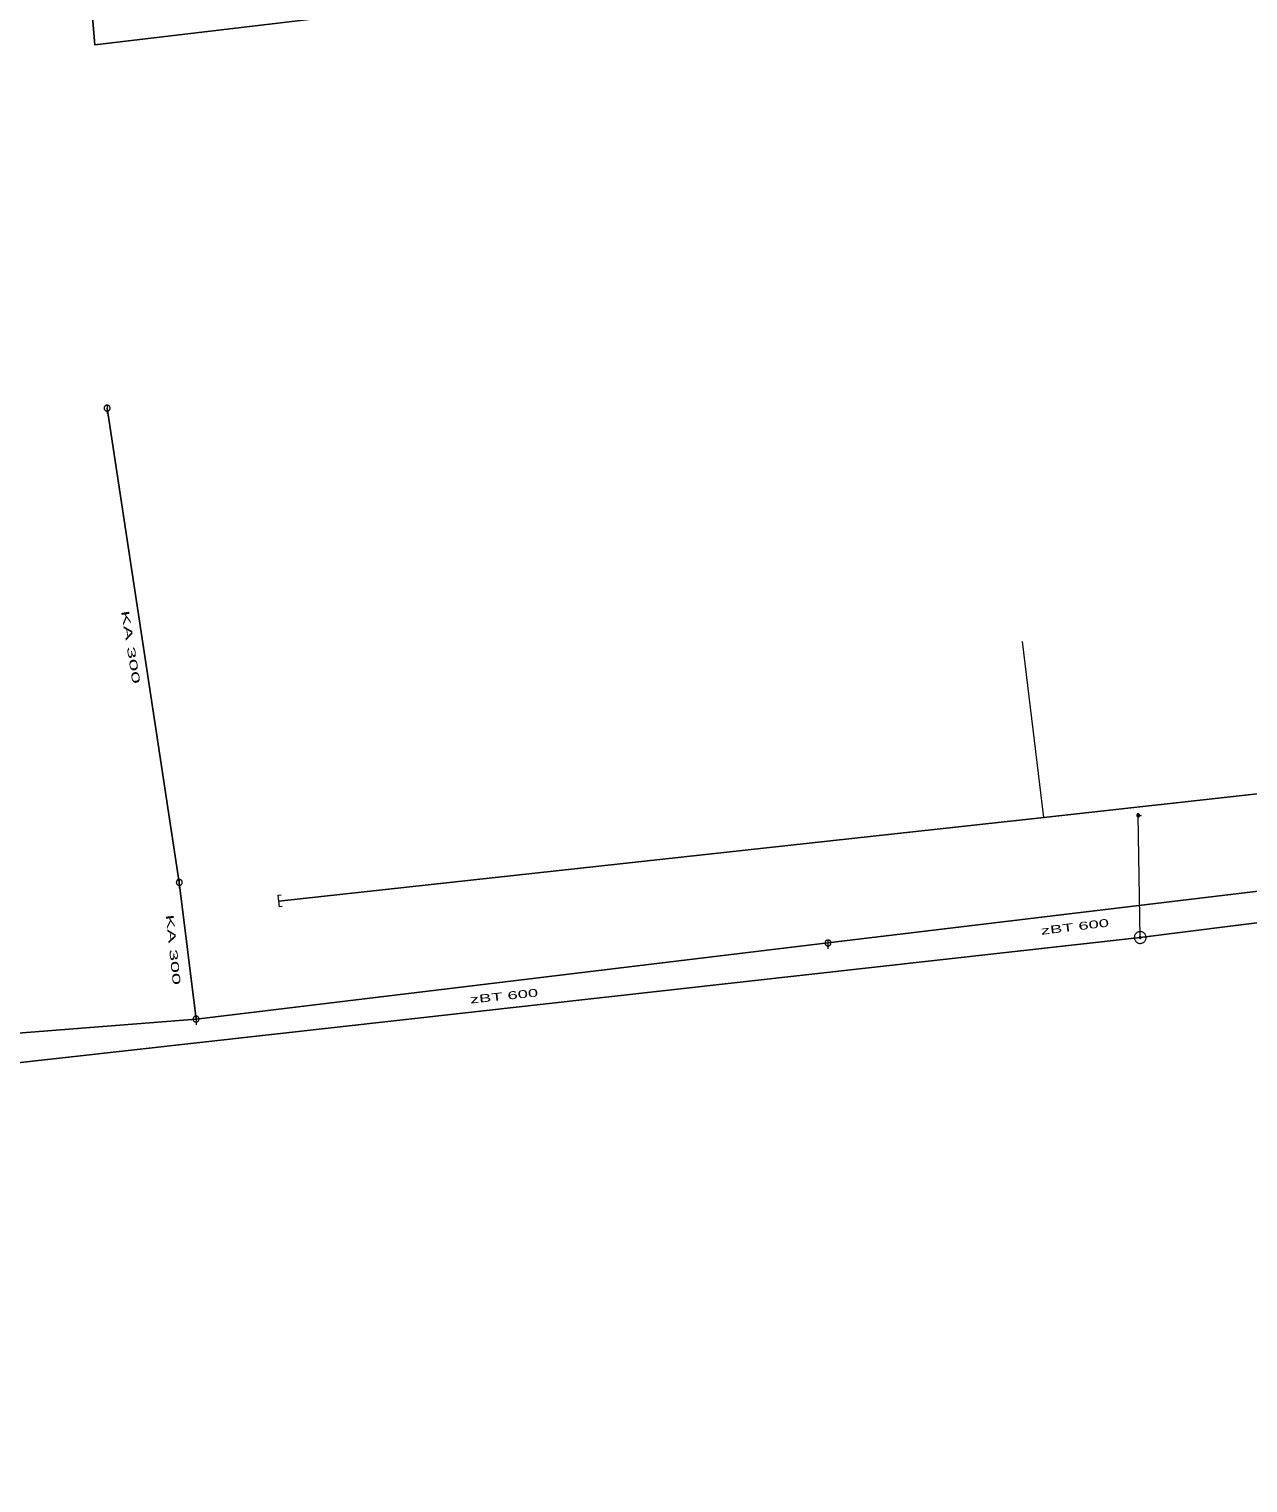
# Model space of a CAD drawing. Extents: x -687515 to -686506, y -974029 to -973461.
# Drawn here: x -686958.8 to -686855.3, y -973700.3 to -973577 of the extents above; entities that cross this region are included whole.
import ezdxf
from ezdxf.enums import TextEntityAlignment as Align

# ---------------------------------------------------------------- set-up
doc = ezdxf.new("R2010")
doc.units = 0
doc.header["$LTSCALE"] = 0.27
for name, color, linetype, lineweight in [('1', 7, 'Continuous', 13), ('13', 7, 'Continuous', 13), ('14', 7, 'Continuous', 25), ('17', 7, 'Continuous', 25), ('22', 7, 'Continuous', 13), ('47', 7, 'Continuous', 13), ('9', 7, 'Continuous', 13)]:
    doc.layers.add(name, color=color, linetype=linetype, lineweight=lineweight)

msp = doc.modelspace()

# ---------------------------------------------------------------- linework, layer by layer
at = {"layer": '13'}
msp.add_line((-686872.671, -973643.865), (-686874.464, -973628.946), dxfattribs=at)
at = {"layer": '14'}
for p, q in [((-686952.143, -973609.144), (-686946.019, -973649.374)), ((-686946.019, -973649.374), (-686944.599, -973660.967)), ((-686848.883, -973649.437), (-686890.976, -973654.512)), ((-686890.976, -973654.512), (-686944.599, -973660.967)), ((-686944.599, -973660.967), (-686987.741, -973664.387))]:
    msp.add_line(p, q, dxfattribs=at)
at = {"layer": '14', "lineweight": 13}
msp.add_line((-686864.483, -973654.051), (-686864.649, -973643.689), dxfattribs=at)
at = {"layer": '17'}
for p, q in [((-686760.428, -973640.909), (-686864.483, -973654.051)), ((-686864.483, -973654.051), (-687064.409, -973676.368))]:
    msp.add_line(p, q, dxfattribs=at)
for points in [[(-686645.309, -973464.46), (-686646.34, -973464.75), (-686680.188, -973471.317), (-686771.188, -973470.317), (-686761.188, -973557.317), (-686894.188, -973571.317), (-686953.188, -973578.317), (-686955.188, -973554.317), (-687116.188, -973577.317), (-687229.188, -973601.317), (-687468.188, -973649.317), (-687458.188, -973700.317)], [(-686937.575, -973650.962), (-686872.671, -973643.864), (-686761.239, -973631.509)]]:
    msp.add_lwpolyline(points, dxfattribs=at)
at = {"layer": '22'}
for p, q in [((-686952.142, -973608.892), (-686952.143, -973609.636)), ((-686946.018, -973649.122), (-686946.019, -973649.865)), ((-686890.975, -973654.26), (-686890.976, -973655.004)), ((-686944.598, -973660.715), (-686944.599, -973661.458))]:
    msp.add_line(p, q, dxfattribs=at)
for points in [[(-686951.891, -973609.144), (-686951.892, -973609.118), (-686951.896, -973609.092), (-686951.902, -973609.066), (-686951.912, -973609.042), (-686951.924, -973609.018), (-686951.938, -973608.996), (-686951.955, -973608.975), (-686951.973, -973608.957), (-686951.994, -973608.94), (-686952.016, -973608.926), (-686952.04, -973608.914), (-686952.064, -973608.904), (-686952.09, -973608.898), (-686952.116, -973608.894), (-686952.142, -973608.892), (-686952.168, -973608.893), (-686952.194, -973608.897), (-686952.22, -973608.903), (-686952.245, -973608.913), (-686952.268, -973608.925), (-686952.29, -973608.939), (-686952.311, -973608.956), (-686952.329, -973608.974), (-686952.346, -973608.995), (-686952.36, -973609.017), (-686952.372, -973609.041), (-686952.382, -973609.065), (-686952.389, -973609.091), (-686952.393, -973609.117), (-686952.395, -973609.143), (-686952.394, -973609.169), (-686952.39, -973609.195), (-686952.383, -973609.221), (-686952.373, -973609.246), (-686952.361, -973609.269), (-686952.347, -973609.291), (-686952.33, -973609.312), (-686952.312, -973609.33), (-686952.291, -973609.347), (-686952.269, -973609.361), (-686952.246, -973609.373), (-686952.221, -973609.383), (-686952.195, -973609.39), (-686952.169, -973609.394), (-686952.143, -973609.396), (-686952.117, -973609.395), (-686952.091, -973609.391), (-686952.065, -973609.384), (-686952.041, -973609.374), (-686952.017, -973609.362), (-686951.995, -973609.348), (-686951.974, -973609.331), (-686951.956, -973609.313), (-686951.939, -973609.292), (-686951.925, -973609.27), (-686951.913, -973609.247), (-686951.903, -973609.222), (-686951.897, -973609.196), (-686951.893, -973609.17)], [(-686945.767, -973649.374), (-686945.768, -973649.348), (-686945.772, -973649.322), (-686945.778, -973649.296), (-686945.788, -973649.272), (-686945.8, -973649.248), (-686945.814, -973649.226), (-686945.831, -973649.205), (-686945.849, -973649.187), (-686945.87, -973649.17), (-686945.892, -973649.156), (-686945.916, -973649.144), (-686945.94, -973649.134), (-686945.966, -973649.128), (-686945.992, -973649.124), (-686946.018, -973649.122), (-686946.044, -973649.123), (-686946.07, -973649.127), (-686946.096, -973649.133), (-686946.121, -973649.143), (-686946.144, -973649.155), (-686946.166, -973649.169), (-686946.187, -973649.186), (-686946.205, -973649.204), (-686946.222, -973649.225), (-686946.236, -973649.247), (-686946.248, -973649.271), (-686946.258, -973649.295), (-686946.265, -973649.321), (-686946.269, -973649.347), (-686946.271, -973649.373), (-686946.27, -973649.399), (-686946.266, -973649.425), (-686946.259, -973649.451), (-686946.249, -973649.476), (-686946.237, -973649.499), (-686946.223, -973649.521), (-686946.206, -973649.542), (-686946.188, -973649.56), (-686946.167, -973649.577), (-686946.145, -973649.591), (-686946.122, -973649.603), (-686946.097, -973649.613), (-686946.071, -973649.62), (-686946.045, -973649.624), (-686946.019, -973649.625), (-686945.993, -973649.625), (-686945.967, -973649.621), (-686945.941, -973649.614), (-686945.917, -973649.604), (-686945.893, -973649.592), (-686945.871, -973649.578), (-686945.85, -973649.561), (-686945.832, -973649.543), (-686945.815, -973649.522), (-686945.801, -973649.5), (-686945.789, -973649.477), (-686945.779, -973649.452), (-686945.773, -973649.426), (-686945.769, -973649.4)], [(-686890.724, -973654.512), (-686890.725, -973654.486), (-686890.729, -973654.46), (-686890.735, -973654.434), (-686890.745, -973654.41), (-686890.757, -973654.386), (-686890.771, -973654.364), (-686890.788, -973654.343), (-686890.806, -973654.325), (-686890.827, -973654.308), (-686890.849, -973654.294), (-686890.873, -973654.282), (-686890.897, -973654.272), (-686890.923, -973654.266), (-686890.949, -973654.262), (-686890.975, -973654.26), (-686891.001, -973654.261), (-686891.027, -973654.265), (-686891.053, -973654.271), (-686891.078, -973654.281), (-686891.101, -973654.293), (-686891.123, -973654.307), (-686891.144, -973654.324), (-686891.162, -973654.342), (-686891.179, -973654.363), (-686891.193, -973654.385), (-686891.205, -973654.409), (-686891.215, -973654.433), (-686891.222, -973654.459), (-686891.226, -973654.485), (-686891.228, -973654.511), (-686891.227, -973654.537), (-686891.223, -973654.563), (-686891.216, -973654.589), (-686891.206, -973654.614), (-686891.194, -973654.637), (-686891.18, -973654.659), (-686891.163, -973654.68), (-686891.145, -973654.698), (-686891.124, -973654.715), (-686891.102, -973654.729), (-686891.079, -973654.741), (-686891.054, -973654.751), (-686891.028, -973654.758), (-686891.002, -973654.762), (-686890.976, -973654.764), (-686890.95, -973654.763), (-686890.924, -973654.759), (-686890.898, -973654.752), (-686890.874, -973654.742), (-686890.85, -973654.73), (-686890.828, -973654.716), (-686890.807, -973654.699), (-686890.789, -973654.681), (-686890.772, -973654.66), (-686890.758, -973654.638), (-686890.746, -973654.615), (-686890.736, -973654.59), (-686890.73, -973654.564), (-686890.726, -973654.538)], [(-686944.347, -973660.967), (-686944.348, -973660.941), (-686944.352, -973660.915), (-686944.358, -973660.889), (-686944.368, -973660.865), (-686944.38, -973660.841), (-686944.394, -973660.819), (-686944.411, -973660.798), (-686944.429, -973660.78), (-686944.45, -973660.763), (-686944.472, -973660.749), (-686944.496, -973660.737), (-686944.52, -973660.727), (-686944.546, -973660.721), (-686944.572, -973660.717), (-686944.598, -973660.715), (-686944.624, -973660.716), (-686944.65, -973660.72), (-686944.676, -973660.726), (-686944.701, -973660.736), (-686944.724, -973660.748), (-686944.746, -973660.762), (-686944.767, -973660.779), (-686944.785, -973660.797), (-686944.802, -973660.818), (-686944.816, -973660.84), (-686944.828, -973660.864), (-686944.838, -973660.888), (-686944.845, -973660.914), (-686944.849, -973660.94), (-686944.851, -973660.966), (-686944.85, -973660.992), (-686944.846, -973661.018), (-686944.839, -973661.044), (-686944.829, -973661.069), (-686944.817, -973661.092), (-686944.803, -973661.114), (-686944.786, -973661.135), (-686944.768, -973661.153), (-686944.747, -973661.17), (-686944.725, -973661.184), (-686944.702, -973661.196), (-686944.677, -973661.206), (-686944.651, -973661.213), (-686944.625, -973661.217), (-686944.599, -973661.218), (-686944.573, -973661.218), (-686944.547, -973661.214), (-686944.521, -973661.207), (-686944.497, -973661.197), (-686944.473, -973661.185), (-686944.451, -973661.171), (-686944.43, -973661.154), (-686944.412, -973661.136), (-686944.395, -973661.115), (-686944.381, -973661.093), (-686944.369, -973661.07), (-686944.359, -973661.045), (-686944.353, -973661.019), (-686944.349, -973660.993)]]:
    msp.add_lwpolyline(points, close=True, dxfattribs=at)
at = {"layer": '47'}
msp.add_lwpolyline([(-686937.277, -973651.432), (-686937.528, -973651.455), (-686937.621, -973650.468), (-686937.37, -973650.444)], dxfattribs=at)
for points in [[(-686863.984, -973654.012), (-686863.991, -973653.96), (-686864.003, -973653.909), (-686864.021, -973653.86), (-686864.043, -973653.813), (-686864.07, -973653.768), (-686864.102, -973653.726), (-686864.138, -973653.689), (-686864.178, -973653.655), (-686864.221, -973653.625), (-686864.267, -973653.6), (-686864.315, -973653.579), (-686864.366, -973653.565), (-686864.417, -973653.555), (-686864.469, -973653.551), (-686864.521, -973653.552), (-686864.573, -973653.559), (-686864.624, -973653.571), (-686864.674, -973653.589), (-686864.72, -973653.611), (-686864.765, -973653.638), (-686864.807, -973653.67), (-686864.845, -973653.706), (-686864.879, -973653.746), (-686864.909, -973653.789), (-686864.933, -973653.835), (-686864.954, -973653.883), (-686864.969, -973653.934), (-686864.978, -973653.985), (-686864.982, -973654.037), (-686864.981, -973654.089), (-686864.974, -973654.141), (-686864.962, -973654.192), (-686864.945, -973654.242), (-686864.922, -973654.288), (-686864.895, -973654.333), (-686864.864, -973654.375), (-686864.828, -973654.413), (-686864.788, -973654.447), (-686864.744, -973654.477), (-686864.698, -973654.501), (-686864.65, -973654.522), (-686864.6, -973654.537), (-686864.548, -973654.546), (-686864.496, -973654.55), (-686864.444, -973654.549), (-686864.392, -973654.542), (-686864.341, -973654.53), (-686864.292, -973654.513), (-686864.245, -973654.49), (-686864.2, -973654.463), (-686864.158, -973654.432), (-686864.121, -973654.396), (-686864.087, -973654.356), (-686864.057, -973654.312), (-686864.032, -973654.266), (-686864.011, -973654.218), (-686863.997, -973654.168), (-686863.987, -973654.116), (-686863.983, -973654.064)], [(-686864.401, -973654.044), (-686864.401, -973654.035), (-686864.404, -973654.027), (-686864.407, -973654.02), (-686864.41, -973654.012), (-686864.415, -973654.004), (-686864.42, -973653.998), (-686864.426, -973653.991), (-686864.432, -973653.985), (-686864.44, -973653.981), (-686864.447, -973653.977), (-686864.455, -973653.973), (-686864.464, -973653.971), (-686864.472, -973653.969), (-686864.48, -973653.968), (-686864.489, -973653.969), (-686864.498, -973653.969), (-686864.506, -973653.972), (-686864.513, -973653.975), (-686864.521, -973653.978), (-686864.529, -973653.983), (-686864.535, -973653.988), (-686864.542, -973653.994), (-686864.548, -973654), (-686864.553, -973654.008), (-686864.556, -973654.015), (-686864.56, -973654.023), (-686864.562, -973654.032), (-686864.564, -973654.04), (-686864.565, -973654.048), (-686864.564, -973654.057), (-686864.564, -973654.066), (-686864.561, -973654.074), (-686864.558, -973654.081), (-686864.555, -973654.089), (-686864.55, -973654.097), (-686864.546, -973654.104), (-686864.539, -973654.11), (-686864.533, -973654.116), (-686864.525, -973654.121), (-686864.518, -973654.124), (-686864.51, -973654.128), (-686864.501, -973654.13), (-686864.493, -973654.132), (-686864.485, -973654.133), (-686864.476, -973654.132), (-686864.467, -973654.132), (-686864.459, -973654.129), (-686864.452, -973654.126), (-686864.444, -973654.123), (-686864.436, -973654.118), (-686864.429, -973654.114), (-686864.423, -973654.107), (-686864.417, -973654.101), (-686864.413, -973654.093), (-686864.409, -973654.086), (-686864.405, -973654.078), (-686864.403, -973654.069), (-686864.401, -973654.061), (-686864.4, -973654.053)]]:
    msp.add_lwpolyline(points, close=True, dxfattribs=at)
at = {"layer": '9'}
msp.add_line((-686864.522, -973643.689), (-686864.397, -973643.689), dxfattribs=at)
for points in [[(-686864.649, -973643.815), (-686864.636, -973643.814), (-686864.623, -973643.812), (-686864.61, -973643.809), (-686864.598, -973643.804), (-686864.586, -973643.798), (-686864.575, -973643.791), (-686864.565, -973643.783), (-686864.555, -973643.773), (-686864.547, -973643.763), (-686864.54, -973643.752), (-686864.534, -973643.74), (-686864.529, -973643.728), (-686864.526, -973643.715), (-686864.524, -973643.702), (-686864.522, -973643.689), (-686864.523, -973643.676), (-686864.525, -973643.663), (-686864.528, -973643.65), (-686864.533, -973643.638), (-686864.539, -973643.626), (-686864.546, -973643.615), (-686864.554, -973643.605), (-686864.564, -973643.595), (-686864.574, -973643.587), (-686864.585, -973643.58), (-686864.597, -973643.574), (-686864.609, -973643.569), (-686864.622, -973643.566), (-686864.635, -973643.564), (-686864.648, -973643.563), (-686864.661, -973643.563), (-686864.674, -973643.565), (-686864.687, -973643.568), (-686864.699, -973643.573), (-686864.711, -973643.579), (-686864.722, -973643.586), (-686864.732, -973643.594), (-686864.742, -973643.604), (-686864.75, -973643.614), (-686864.757, -973643.625), (-686864.763, -973643.637), (-686864.768, -973643.649), (-686864.771, -973643.662), (-686864.773, -973643.675), (-686864.775, -973643.688), (-686864.774, -973643.701), (-686864.772, -973643.714), (-686864.769, -973643.727), (-686864.764, -973643.739), (-686864.758, -973643.751), (-686864.751, -973643.762), (-686864.743, -973643.772), (-686864.733, -973643.782), (-686864.723, -973643.79), (-686864.712, -973643.797), (-686864.7, -973643.803), (-686864.688, -973643.808), (-686864.675, -973643.811), (-686864.662, -973643.813)], [(-686864.649, -973643.795), (-686864.638, -973643.795), (-686864.627, -973643.793), (-686864.616, -973643.79), (-686864.606, -973643.786), (-686864.596, -973643.781), (-686864.587, -973643.775), (-686864.578, -973643.768), (-686864.57, -973643.76), (-686864.563, -973643.751), (-686864.557, -973643.742), (-686864.552, -973643.732), (-686864.548, -973643.722), (-686864.545, -973643.711), (-686864.543, -973643.7), (-686864.543, -973643.689), (-686864.542, -973643.678), (-686864.544, -973643.667), (-686864.547, -973643.656), (-686864.551, -973643.646), (-686864.556, -973643.636), (-686864.562, -973643.627), (-686864.569, -973643.618), (-686864.577, -973643.61), (-686864.586, -973643.603), (-686864.595, -973643.597), (-686864.605, -973643.592), (-686864.615, -973643.588), (-686864.626, -973643.585), (-686864.637, -973643.583), (-686864.648, -973643.583), (-686864.659, -973643.582), (-686864.67, -973643.584), (-686864.681, -973643.587), (-686864.691, -973643.591), (-686864.701, -973643.596), (-686864.71, -973643.602), (-686864.719, -973643.609), (-686864.727, -973643.617), (-686864.734, -973643.626), (-686864.74, -973643.635), (-686864.745, -973643.645), (-686864.749, -973643.655), (-686864.752, -973643.666), (-686864.754, -973643.677), (-686864.755, -973643.688), (-686864.755, -973643.699), (-686864.753, -973643.71), (-686864.75, -973643.721), (-686864.746, -973643.731), (-686864.741, -973643.741), (-686864.735, -973643.75), (-686864.728, -973643.759), (-686864.72, -973643.767), (-686864.711, -973643.774), (-686864.702, -973643.78), (-686864.692, -973643.785), (-686864.682, -973643.789), (-686864.671, -973643.792), (-686864.66, -973643.794)], [(-686864.649, -973643.776), (-686864.64, -973643.775), (-686864.631, -973643.774), (-686864.622, -973643.771), (-686864.614, -973643.768), (-686864.606, -973643.764), (-686864.598, -973643.759), (-686864.591, -973643.753), (-686864.585, -973643.747), (-686864.579, -973643.74), (-686864.574, -973643.732), (-686864.57, -973643.724), (-686864.567, -973643.716), (-686864.564, -973643.707), (-686864.563, -973643.698), (-686864.561, -973643.689), (-686864.562, -973643.68), (-686864.563, -973643.671), (-686864.566, -973643.662), (-686864.569, -973643.654), (-686864.573, -973643.646), (-686864.578, -973643.638), (-686864.584, -973643.631), (-686864.59, -973643.625), (-686864.597, -973643.619), (-686864.605, -973643.614), (-686864.613, -973643.61), (-686864.621, -973643.607), (-686864.63, -973643.604), (-686864.639, -973643.603), (-686864.648, -973643.602), (-686864.657, -973643.602), (-686864.666, -973643.603), (-686864.675, -973643.606), (-686864.683, -973643.609), (-686864.691, -973643.613), (-686864.699, -973643.618), (-686864.706, -973643.624), (-686864.712, -973643.63), (-686864.718, -973643.637), (-686864.723, -973643.645), (-686864.727, -973643.653), (-686864.73, -973643.661), (-686864.733, -973643.67), (-686864.734, -973643.679), (-686864.736, -973643.688), (-686864.735, -973643.697), (-686864.734, -973643.706), (-686864.731, -973643.715), (-686864.728, -973643.723), (-686864.724, -973643.731), (-686864.719, -973643.739), (-686864.713, -973643.746), (-686864.707, -973643.752), (-686864.7, -973643.758), (-686864.692, -973643.763), (-686864.684, -973643.767), (-686864.676, -973643.77), (-686864.667, -973643.773), (-686864.658, -973643.774)], [(-686864.649, -973643.756), (-686864.642, -973643.756), (-686864.635, -973643.754), (-686864.628, -973643.753), (-686864.622, -973643.75), (-686864.616, -973643.747), (-686864.61, -973643.743), (-686864.604, -973643.739), (-686864.599, -973643.734), (-686864.595, -973643.728), (-686864.591, -973643.722), (-686864.588, -973643.716), (-686864.585, -973643.71), (-686864.584, -973643.703), (-686864.582, -973643.696), (-686864.581, -973643.689), (-686864.581, -973643.682), (-686864.583, -973643.675), (-686864.584, -973643.668), (-686864.587, -973643.662), (-686864.59, -973643.655), (-686864.594, -973643.65), (-686864.598, -973643.644), (-686864.603, -973643.639), (-686864.609, -973643.635), (-686864.615, -973643.631), (-686864.621, -973643.628), (-686864.627, -973643.625), (-686864.634, -973643.623), (-686864.641, -973643.622), (-686864.648, -973643.622), (-686864.655, -973643.621), (-686864.662, -973643.622), (-686864.669, -973643.624), (-686864.675, -973643.627), (-686864.682, -973643.63), (-686864.687, -973643.634), (-686864.693, -973643.638), (-686864.698, -973643.643), (-686864.702, -973643.649), (-686864.706, -973643.654), (-686864.709, -973643.661), (-686864.712, -973643.667), (-686864.714, -973643.674), (-686864.715, -973643.681), (-686864.716, -973643.688), (-686864.716, -973643.695), (-686864.715, -973643.702), (-686864.713, -973643.709), (-686864.71, -973643.715), (-686864.707, -973643.721), (-686864.703, -973643.727), (-686864.699, -973643.733), (-686864.694, -973643.738), (-686864.688, -973643.742), (-686864.683, -973643.746), (-686864.676, -973643.749), (-686864.67, -973643.752), (-686864.663, -973643.753), (-686864.656, -973643.755)], [(-686864.649, -973643.736), (-686864.644, -973643.736), (-686864.639, -973643.735), (-686864.634, -973643.734), (-686864.63, -973643.732), (-686864.625, -973643.73), (-686864.621, -973643.727), (-686864.618, -973643.724), (-686864.614, -973643.72), (-686864.611, -973643.717), (-686864.608, -973643.713), (-686864.606, -973643.708), (-686864.604, -973643.704), (-686864.603, -973643.699), (-686864.602, -973643.694), (-686864.602, -973643.689), (-686864.601, -973643.684), (-686864.602, -973643.679), (-686864.603, -973643.674), (-686864.605, -973643.67), (-686864.607, -973643.665), (-686864.61, -973643.661), (-686864.613, -973643.657), (-686864.617, -973643.654), (-686864.62, -973643.651), (-686864.624, -973643.648), (-686864.629, -973643.646), (-686864.633, -973643.644), (-686864.638, -973643.643), (-686864.643, -973643.642), (-686864.648, -973643.642), (-686864.653, -973643.641), (-686864.658, -973643.642), (-686864.663, -973643.643), (-686864.667, -973643.645), (-686864.672, -973643.647), (-686864.676, -973643.65), (-686864.68, -973643.653), (-686864.683, -973643.656), (-686864.686, -973643.66), (-686864.689, -973643.664), (-686864.691, -973643.669), (-686864.693, -973643.673), (-686864.694, -973643.678), (-686864.695, -973643.683), (-686864.696, -973643.688), (-686864.696, -973643.693), (-686864.695, -973643.698), (-686864.694, -973643.703), (-686864.692, -973643.707), (-686864.69, -973643.712), (-686864.687, -973643.716), (-686864.684, -973643.719), (-686864.681, -973643.723), (-686864.677, -973643.726), (-686864.673, -973643.729), (-686864.668, -973643.731), (-686864.664, -973643.733), (-686864.659, -973643.734), (-686864.654, -973643.735)], [(-686864.649, -973643.716), (-686864.646, -973643.716), (-686864.643, -973643.716), (-686864.641, -973643.715), (-686864.638, -973643.714), (-686864.635, -973643.713), (-686864.633, -973643.711), (-686864.631, -973643.709), (-686864.629, -973643.707), (-686864.627, -973643.705), (-686864.625, -973643.703), (-686864.624, -973643.7), (-686864.623, -973643.697), (-686864.622, -973643.695), (-686864.622, -973643.692), (-686864.622, -973643.689), (-686864.621, -973643.686), (-686864.621, -973643.683), (-686864.622, -973643.68), (-686864.623, -973643.678), (-686864.624, -973643.675), (-686864.626, -973643.673), (-686864.628, -973643.67), (-686864.63, -973643.668), (-686864.632, -973643.667), (-686864.634, -973643.665), (-686864.637, -973643.664), (-686864.64, -973643.663), (-686864.642, -973643.662), (-686864.645, -973643.662), (-686864.648, -973643.661), (-686864.651, -973643.661), (-686864.654, -973643.661), (-686864.657, -973643.662), (-686864.659, -973643.663), (-686864.662, -973643.664), (-686864.664, -973643.666), (-686864.667, -973643.667), (-686864.669, -973643.669), (-686864.67, -973643.672), (-686864.672, -973643.674), (-686864.673, -973643.677), (-686864.674, -973643.679), (-686864.675, -973643.682), (-686864.675, -973643.685), (-686864.677, -973643.688), (-686864.676, -973643.691), (-686864.676, -973643.694), (-686864.675, -973643.696), (-686864.674, -973643.699), (-686864.673, -973643.702), (-686864.671, -973643.704), (-686864.67, -973643.706), (-686864.668, -973643.708), (-686864.665, -973643.71), (-686864.663, -973643.712), (-686864.66, -973643.713), (-686864.658, -973643.714), (-686864.655, -973643.715), (-686864.652, -973643.715)], [(-686864.649, -973643.697), (-686864.648, -973643.697), (-686864.647, -973643.697), (-686864.647, -973643.696), (-686864.646, -973643.696), (-686864.645, -973643.696), (-686864.644, -973643.695), (-686864.644, -973643.695), (-686864.643, -973643.694), (-686864.643, -973643.694), (-686864.642, -973643.693), (-686864.642, -973643.692), (-686864.642, -973643.691), (-686864.641, -973643.691), (-686864.641, -973643.69), (-686864.641, -973643.689), (-686864.641, -973643.688), (-686864.641, -973643.687), (-686864.641, -973643.687), (-686864.641, -973643.686), (-686864.641, -973643.685), (-686864.642, -973643.684), (-686864.642, -973643.684), (-686864.643, -973643.683), (-686864.643, -973643.683), (-686864.644, -973643.682), (-686864.645, -973643.682), (-686864.646, -973643.681), (-686864.646, -973643.681), (-686864.647, -973643.681), (-686864.648, -973643.681), (-686864.649, -973643.681), (-686864.65, -973643.681), (-686864.65, -973643.681), (-686864.651, -973643.681), (-686864.652, -973643.681), (-686864.653, -973643.682), (-686864.653, -973643.682), (-686864.654, -973643.683), (-686864.654, -973643.683), (-686864.655, -973643.684), (-686864.655, -973643.685), (-686864.656, -973643.686), (-686864.656, -973643.686), (-686864.656, -973643.687), (-686864.657, -973643.688), (-686864.657, -973643.689), (-686864.657, -973643.69), (-686864.657, -973643.69), (-686864.656, -973643.691), (-686864.656, -973643.692), (-686864.655, -973643.693), (-686864.655, -973643.693), (-686864.654, -973643.694), (-686864.654, -973643.694), (-686864.653, -973643.695), (-686864.652, -973643.695), (-686864.651, -973643.695), (-686864.651, -973643.696), (-686864.65, -973643.696)]]:
    msp.add_lwpolyline(points, close=True, dxfattribs=at)
msp.add_lwpolyline([(-686864.431, -973643.658), (-686864.397, -973643.689), (-686864.432, -973643.72)], dxfattribs=at)

# ---------------------------------------------------------------- texts
at = {"layer": '1'}
for s, rotation, width, p in [('KA 300', 279, 2.15, (-686950.469, -973629.466)), ('KA 300', 276, 2.05, (-686946.867, -973655.119)), ('zBT 600 ', 7, 1.75, (-686869.768, -973653.44)), ('zBT 600 ', 6, 1.75, (-686918.218, -973659.328))]:
    msp.add_text(s, height=0.6667, rotation=rotation, dxfattribs=dict(at, width=width)).set_placement(p, align=Align.CENTER)

doc.saveas('drawing.dxf')
